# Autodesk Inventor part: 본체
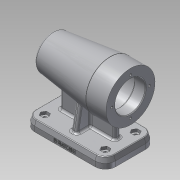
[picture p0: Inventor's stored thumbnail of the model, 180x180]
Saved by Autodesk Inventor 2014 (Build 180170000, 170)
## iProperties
Created: 2017-01
Part Number: 본체
Material: 알루미늄 6061
Document SubType Name: Modeling
Designer: Administrator
Mass: 795.171 g
Surface Area: 661.819 cm^2
Volume: 293.421 cm^3
Density: 2.71 g/cm^3
Appearance: 알루미늄 - 평지
Author: Administrator
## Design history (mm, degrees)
sketch "스케치1"
  geometry: L1 (-56, 35)-(56, 35); L2 (56, 35)-(56, -35); L3 (56, -35)-(-56, -35); L4 (-56, -35)-(-56, 35); L5 (-56, 35)-(56, -35); L6 (56, 35)-(-56, -35); 1 further point
  constraints: 12 end point, 2 midpoint, 2 parallel, 1 horizontal, 1 perpendicular
  dimensions: "d0" = 70 distance of L1.end L2.end; "d1" = 112 distance of L1.start L1.end
extrude "돌출1" new body sketch "스케치1" distance "d2" = 14; taper "d3" = 0 deg
fillet "모깎기1" dims "d4" = 14
chamfer "모따기1" distance "d5" = 7; stored, may be unused: second distance "d6" = 2, angle "d7" = 15 deg
fillet "모깎기2" dims "d8" = 1
sketch "스케치2"
  geometry: L1 (-38, 4)-(38, 4); L2 (38, 4)-(38, -4); L3 (38, -4)-(-38, -4); L4 (-38, -4)-(-38, 4); L5 (-38, 4)-(38, -4); L6 (38, 4)-(-38, -4); L7 (56, 21)-(56, -21) reference; L8 (-56, 21)-(-56, -21) reference; L9 (-4, 23)-(4, 23); L10 (4, 23)-(4, -23); L11 (4, -23)-(-4, -23); L12 (-4, -23)-(-4, 23); L13 (-4, 23)-(4, -23); L14 (4, 23)-(-4, -23); 1 further point
  constraints: 24 end point, 4 midpoint, 4 parallel, 2 horizontal, 2 perpendicular
  dimensions: "d9" = 76 distance of L1.start L1.end; "d12" = 8 distance of L3.end L1.start; "d13" = 8 distance of L9.start L9.end; "d14" = 46 distance of L9.end L10.end
extrude "돌출2" join sketch "스케치2" distance "d15" = 74; taper "d16" = 0 deg
feature "면 기울기1" dims angle "d17" = 10 deg
sketch "스케치3"
  geometry: L1 (56, 74)-(-56, 74); L2 (56, 74)-(56, 108); L3 (56, 108)-(28, 108); L4 (28, 108)-(-52.27, 98.144); L5 (42, 0)-(-42, 0) reference; A1 r 80 centre (24, 74) between (-52.27, 98.144) and (-56, 74); 3 further points
  constraints: 8 end point, 2 midpoint, 2 perpendicular, 2 point on circle, 1 centre point, 1 horizontal, 1 horizontal alignment, 1 vertical alignment
  dimensions: "d18" = 28 distance of L2.end L3.end; "d19" = 80 radius of A1; "d20" = 112 distance of L1.start L1.end; "d21" = 7 deg angle of L3 L4; "d22" = 74 distance between parallel lines of L5 L1; "d23" = 68 diameter of L3 L1
revolve "회전1" sketch "스케치3" stored, may be unused: angle "d24" = 90 deg
sketch "스케치4"
  geometry: L1 (56, 40)-(56, 108) reference; L2 (56, 74)-(41, 74); L3 (41, 74)-(41, 95); L4 (41, 95)-(56, 95); L5 (56, 95)-(56, 74); L6 (41, 74)-(-13, 74); L7 (-13, 74)-(-13, 98); L8 (-13, 98)-(41, 98); L9 (41, 98)-(41, 74); L10 (-13, 74)-(-25, 74); L11 (-25, 74)-(-25, 95); L12 (-25, 95)-(-13, 95); L13 (-13, 95)-(-13, 74); L14 (-25, 74)-(-43, 74); L15 (-43, 74)-(-43, 91.5); L16 (-43, 91.5)-(-25, 91.5); L17 (-25, 91.5)-(-25, 74); L18 (-43, 74)-(-47, 74); L19 (-47, 74)-(-47, 90); L20 (-47, 90)-(-43, 90); L21 (-43, 90)-(-43, 74); L22 (-47, 74)-(-50, 74); L23 (-50, 74)-(-50, 84.5); L24 (-50, 84.5)-(-47, 84.5); L25 (-47, 84.5)-(-47, 74); A1 r 80 centre (24, 74) between (-52.27, 98.144) and (-52.27, 49.856) reference; 1 further point
  constraints: 48 end point, 12 parallel, 6 horizontal, 6 perpendicular, 1 midpoint
  dimensions: "d25" = 15 distance of L3.end L4.end; "d26" = 54 distance of L7.end L8.end; "d27" = 12 distance of L11.end L12.end; "d28" = 18 distance of L15.end L16.end; "d29" = 4 distance of L19.end L20.end; "d30" = 3 distance of L23.end L24.end; "d31" = 42 diameter of L4 L2; "d32" = 48 diameter of L8 L6; "d33" = 42 diameter of L12 L10; "d34" = 35 diameter of L16 L14; "d35" = 32 diameter of L20 L18; "d36" = 21 diameter of L24 L22
revolve "회전2" sketch "스케치4" stored, may be unused: angle "d37" = 90 deg
fillet "모깎기3" dims "d38" = 3
fillet "모깎기4" dims "d39" = 0.3
fillet "모깎기5" dims "d40" = 3
chamfer "모따기2" distance "d41" = 1; stored, may be unused: second distance "d42" = 2, angle "d43" = 15 deg
fillet "모깎기6" dims "d44" = 3
fillet "모깎기9" dims "d76" = 3
sketch "스케치6"
  geometry: C1 r 22 at (0, 0) reference; A1 r 26 centre (0, 0) between (26, 0) and (0, 26); 3 further points
  constraints: 4 point on circle, 1 centre point
  dimensions: "d47" = 52 diameter of A1
hole "구멍1" sketch "스케치6" at (26, 0), (0, 26), (0, -26), (-26, 0) diameter "d48" = 3.242; stored, may be unused: countersink angle "d52" = 90 deg, drill point angle "d54" = 118 deg; dims "d49" = 8, "d50" = 4, "d51" = 2, "d53" = 11
fillet "모깎기8" dims "d55" = 3
sketch "스케치7"
  geometry: L1 (-42, 21)-(42, 21); L2 (42, 21)-(42, -21); L3 (42, -21)-(-42, -21); L4 (-42, -21)-(-42, 21); L5 (-42, 21)-(42, -21); L6 (42, 21)-(-42, -21); L7 (-39.113, 26)-(-36.226, 21); L8 (-36.226, 21)-(-39.113, 16); L9 (-39.113, 16)-(-44.887, 16); L10 (-44.887, 16)-(-47.774, 21); L11 (-47.774, 21)-(-44.887, 26); L12 (-44.887, 26)-(-39.113, 26); L13 (-39.113, -16)-(-36.226, -21); L14 (-36.226, -21)-(-39.113, -26); L15 (-39.113, -26)-(-44.887, -26); L16 (-44.887, -26)-(-47.774, -21); L17 (-47.774, -21)-(-44.887, -16); L18 (-44.887, -16)-(-39.113, -16); L19 (44.887, 26)-(47.774, 21); L20 (47.774, 21)-(44.887, 16); L21 (44.887, 16)-(39.113, 16); L22 (39.113, 16)-(36.226, 21); L23 (36.226, 21)-(39.113, 26); L24 (39.113, 26)-(44.887, 26); L25 (44.887, -16)-(47.774, -21); L26 (47.774, -21)-(44.887, -26); L27 (44.887, -26)-(39.113, -26); L28 (39.113, -26)-(36.226, -21); L29 (36.226, -21)-(39.113, -16); L30 (39.113, -16)-(44.887, -16); 13 further points
  constraints: 60 end point, 6 midpoint, 4 coincident, 2 parallel, 1 horizontal, 1 perpendicular, 1 point on line, 52 other
  dimensions: "d56" = 42 distance of L1.end L2.end; "d57" = 84 distance of L1.start L1.end
extrude "돌출3" cut sketch "스케치7" distance "d62" = 4; taper "d63" = 0 deg
sketch "스케치8"
  geometry: L1 (-42, -21)-(42, -21); L2 (42, -21)-(42, 21); L3 (42, 21)-(-42, 21); L4 (-42, 21)-(-42, -21); L5 (-42, -21)-(42, 21); L6 (42, -21)-(-42, 21); A1 r 11.357 centre (42, 21) between (53.357, 21) and (42, 32.357) reference; 5 further points
  constraints: 12 end point, 4 coincident, 2 midpoint, 2 parallel, 1 horizontal, 1 perpendicular
hole "구멍2" sketch "스케치8" at (-42, 21), (42, 21), (42, -21), (-42, -21) diameter "d64" = 5; stored, may be unused: countersink angle "d68" = 90 deg, drill point angle "d70" = 118 deg; dims "d65" = 8, "d66" = 4, "d67" = 2, "d69" = 11
node "작업 평면1"
sketch "스케치9"
  geometry: L1 (56, 0)-(56, 7) reference; L2 (42, 0)-(-42, 0) reference; 2 further points
  constraints: 1 other
  dimensions: "d72" = 56 distance from line of L1 point (0, 4); "d73" = 4 distance from line of point (0, 4) L2
feature "엠보싱1" sketch "스케치9" dims "d0" = 70, "d1" = 112, "d74" = 0.5, "d75" = 0
sketch "스케치10"
  geometry: 1 further point
fillet "모깎기10" dims "d77" = 3
node "솔리드1"
other parameters: "d71" = 47.25
